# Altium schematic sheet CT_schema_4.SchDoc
size 143 x 123 mm
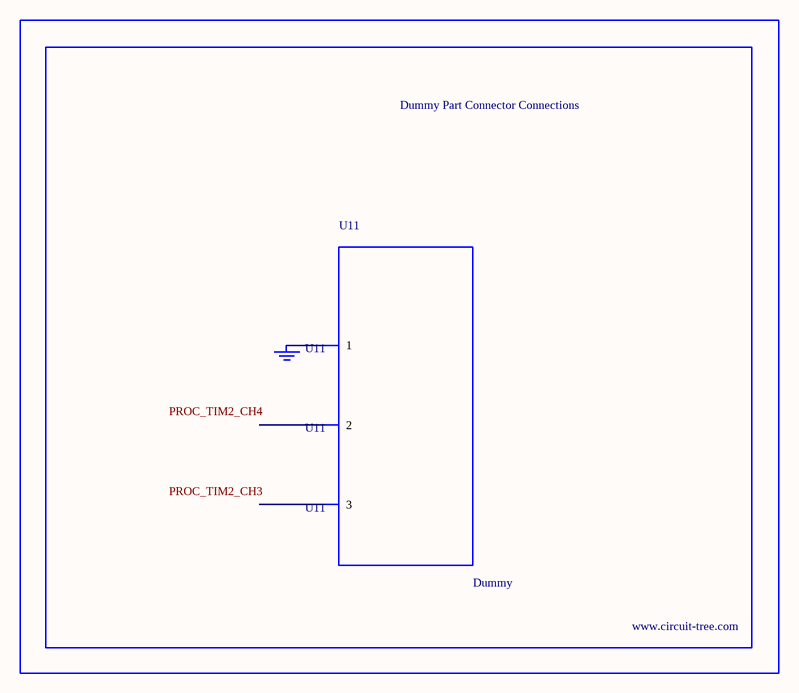
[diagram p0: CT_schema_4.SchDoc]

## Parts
BORDER3  (no value)
GND_INSTANCE_3_0  (no value)
U11  Dummy  [DUMMY_PACKAGE_113]

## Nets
NetGND_INSTANCE_3_0_0: GND_INSTANCE_3_0.0(GND) U11.1

Not connected (* = marked no-connect by the designer): U11 2 3

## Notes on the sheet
- Labels drawn without touching a wire or pin: PROC_TIM2_CH3, PROC_TIM2_CH4

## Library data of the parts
BORDER3 = BORDER_PAGE3
GND_INSTANCE_3_0 = GND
